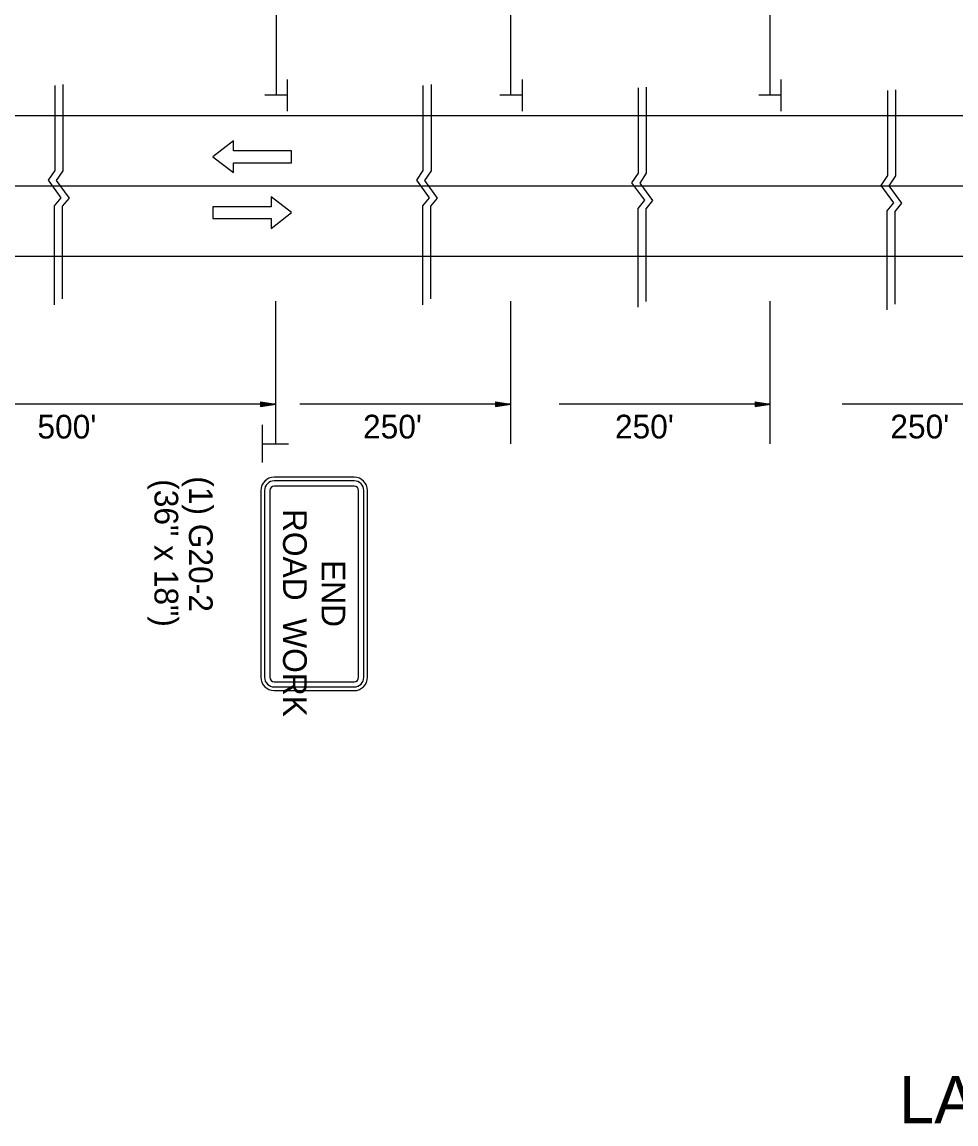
# Model space of a CAD drawing. Extents: x 1926586 to 1930787, y 596452 to 599566.
# Drawn here: x 1928093.9 to 1928330.2, y 596716.6 to 596995.4 of the extents above; entities that cross this region are included whole.
import ezdxf

# ---------------------------------------------------------------- set-up
doc = ezdxf.new("R2010")
doc.units = 0
for name, color, linetype in [('Default', 7, 'Continuous'), ('P_TC_Signs_Temporary', 7, 'Continuous'), ('R_Border', 7, 'Continuous'), ('R_Striping', 7, 'Continuous')]:
    doc.layers.add(name, color=color, linetype=linetype)

msp = doc.modelspace()

# ---------------------------------------------------------------- linework, layer by layer
at = {"layer": 'Default'}
for p, q in [((1928160.97, 596980.87), (1928160.97, 596972.87)), ((1928220.43, 596980.87), (1928220.43, 596972.87)), ((1928285.91, 596980.87), (1928285.91, 596972.87)), ((1928160.86, 596976.89), (1928155.39, 596976.89)), ((1928220.31, 596976.89), (1928214.85, 596976.89)), ((1928285.79, 596976.89), (1928280.32, 596976.89)), ((1927876.38, 596971.79), (1928531.8, 596971.74)), ((1927875.66, 596954), (1928669.64, 596953.94)), ((1927876.15, 596936.21), (1928531.8, 596936.16)), ((1928158.12, 596888.7), (1928158.12, 596924.73)), ((1928217.58, 596888.7), (1928217.58, 596924.73)), ((1928283.23, 596888.7), (1928283.23, 596924.73)), ((1928154.29, 596899.32), (1928158.12, 596898.74)), ((1928154.29, 596899.32), (1928154.29, 596898.16)), ((1928154.29, 596899.22), (1928157.48, 596898.74)), ((1928154.29, 596899.12), (1928156.82, 596898.74)), ((1928154.29, 596899.03), (1928156.18, 596898.74)), ((1928154.29, 596898.93), (1928155.53, 596898.74)), ((1928213.74, 596899.32), (1928217.58, 596898.74)), ((1928213.74, 596899.32), (1928213.74, 596898.16)), ((1928213.74, 596899.22), (1928216.94, 596898.74)), ((1928213.74, 596899.12), (1928216.28, 596898.74)), ((1928213.74, 596899.03), (1928215.64, 596898.74)), ((1928213.74, 596898.93), (1928214.99, 596898.74)), ((1928279.39, 596899.32), (1928283.23, 596898.74)), ((1928279.39, 596899.32), (1928279.39, 596898.16)), ((1928279.39, 596899.22), (1928282.59, 596898.74)), ((1928279.39, 596899.12), (1928281.93, 596898.74)), ((1928279.39, 596899.03), (1928281.29, 596898.74)), ((1928279.39, 596898.93), (1928280.64, 596898.74)), ((1928158.12, 596898.74), (1928058.37, 596898.74)), ((1928154.29, 596898.83), (1928154.89, 596898.74)), ((1928154.29, 596898.16), (1928158.12, 596898.74)), ((1928154.29, 596898.55), (1928155.53, 596898.74)), ((1928154.29, 596898.36), (1928156.82, 596898.74)), ((1928154.29, 596898.26), (1928157.48, 596898.74)), ((1928154.29, 596898.45), (1928156.18, 596898.74)), ((1928154.29, 596898.65), (1928154.89, 596898.74)), ((1928217.58, 596898.74), (1928164.18, 596898.74)), ((1928213.74, 596898.83), (1928214.35, 596898.74)), ((1928213.74, 596898.16), (1928217.58, 596898.74)), ((1928213.74, 596898.55), (1928214.99, 596898.74)), ((1928213.74, 596898.36), (1928216.28, 596898.74)), ((1928213.74, 596898.26), (1928216.94, 596898.74)), ((1928213.74, 596898.45), (1928215.64, 596898.74)), ((1928213.74, 596898.65), (1928214.35, 596898.74)), ((1928283.23, 596898.74), (1928229.83, 596898.74)), ((1928279.39, 596898.83), (1928280, 596898.74)), ((1928279.39, 596898.16), (1928283.23, 596898.74)), ((1928279.39, 596898.55), (1928280.64, 596898.74)), ((1928279.39, 596898.36), (1928281.93, 596898.74)), ((1928279.39, 596898.26), (1928282.59, 596898.74)), ((1928279.39, 596898.45), (1928281.29, 596898.74)), ((1928279.39, 596898.65), (1928280, 596898.74)), ((1928354.82, 596898.74), (1928301.42, 596898.74)), ((1928154.74, 596883.98), (1928154.74, 596893.47)), ((1928154.89, 596888.7), (1928161.36, 596888.7))]:
    msp.add_line(p, q, dxfattribs=at)
for points in [[(1928102.19, 596979.37), (1928102.19, 596957.85), (1928100.53, 596955.38), (1928103.77, 596950.95), (1928102.07, 596948.9), (1928102.06, 596923.88)], [(1928104.24, 596979.57), (1928104.24, 596957.77), (1928102.58, 596955.29), (1928105.81, 596950.86), (1928104.11, 596948.82), (1928104.11, 596925.32)], [(1928195.36, 596979.37), (1928195.36, 596957.85), (1928193.7, 596955.38), (1928196.93, 596950.95), (1928195.23, 596948.9), (1928195.23, 596923.88)], [(1928197.4, 596979.57), (1928197.4, 596957.77), (1928195.74, 596955.29), (1928198.98, 596950.86), (1928197.27, 596948.82), (1928197.27, 596925.32)], [(1928249.82, 596978.73), (1928249.82, 596957.2), (1928248.16, 596954.73), (1928251.4, 596950.3), (1928249.69, 596948.26), (1928249.69, 596923.23)], [(1928251.87, 596978.92), (1928251.87, 596957.12), (1928250.2, 596954.65), (1928253.44, 596950.22), (1928251.74, 596948.17), (1928251.73, 596924.67)], [(1928312.86, 596978.06), (1928312.86, 596956.53), (1928311.2, 596954.06), (1928314.44, 596949.63), (1928312.73, 596947.59), (1928312.73, 596922.56)], [(1928314.91, 596978.25), (1928314.91, 596956.45), (1928313.24, 596953.98), (1928316.48, 596949.55), (1928314.78, 596947.5), (1928314.77, 596924)]]:
    msp.add_lwpolyline(points, dxfattribs=at)
at = {"layer": 'P_TC_Signs_Temporary'}
for p, q in [((1928177.96, 596880.23), (1928157.71, 596880.23)), ((1928154.33, 596876.86), (1928154.33, 596829.61)), ((1928155.27, 596876.86), (1928155.27, 596829.61)), ((1928156.58, 596876.86), (1928156.58, 596829.61)), ((1928177.96, 596879.29), (1928157.71, 596879.29)), ((1928177.96, 596877.98), (1928157.71, 596877.98)), ((1928179.08, 596829.61), (1928179.08, 596876.86)), ((1928180.4, 596829.61), (1928180.4, 596876.86)), ((1928181.33, 596829.61), (1928181.33, 596876.86)), ((1928157.71, 596828.48), (1928177.96, 596828.48)), ((1928157.71, 596827.17), (1928177.96, 596827.17)), ((1928157.71, 596826.23), (1928177.96, 596826.23))]:
    msp.add_line(p, q, dxfattribs=at)
for centre, radius, start, end in [((1928157.71, 596876.86), 3.38, 90, 180), ((1928177.96, 596876.86), 3.37, 360, 90), ((1928157.71, 596876.86), 2.44, 90, 180), ((1928157.71, 596876.86), 1.13, 90, 180), ((1928177.96, 596876.86), 2.44, 360, 90), ((1928177.96, 596876.86), 1.13, 360, 90), ((1928157.71, 596829.61), 3.37, 180, 270), ((1928157.71, 596829.61), 2.44, 180, 270), ((1928157.71, 596829.61), 1.13, 180, 270), ((1928177.96, 596829.61), 2.44, 270, 360), ((1928177.96, 596829.61), 1.13, 270, 360), ((1928177.96, 596829.61), 3.38, 270, 360)]:
    msp.add_arc(centre, radius, start, end, dxfattribs=at)
at = {"layer": 'R_Border'}
for p, q in [((1928158.3, 596976.89), (1928158.3, 597053.66)), ((1928283.23, 596976.89), (1928283.23, 597051.44)), ((1928217.58, 596976.89), (1928217.58, 597010.2))]:
    msp.add_line(p, q, dxfattribs=at)
at = {"layer": 'R_Striping'}
for points in [[(1928147.39, 596965.3), (1928142.2, 596961.3), (1928147.39, 596957.3), (1928147.39, 596959.8), (1928162.11, 596959.8), (1928162.11, 596962.8), (1928147.39, 596962.8)], [(1928156.91, 596943.18), (1928162.11, 596947.18), (1928156.91, 596951.18), (1928156.91, 596948.68), (1928142.2, 596948.68), (1928142.2, 596945.68), (1928156.91, 596945.68)]]:
    msp.add_lwpolyline(points, close=True, dxfattribs=at)

# ---------------------------------------------------------------- texts
at = {"layer": 'Default'}
for s, height, rotation, p in [("500'", 6, 359.9922, (1928097.81, 596890.02)), ("250'", 6, 359.9922, (1928180.19, 596890.03)), ("250'", 6, 359.9922, (1928243.93, 596890.04)), ("250'", 6, 359.9922, (1928313.61, 596890.05)), ('LANE CLOSURE WITH PORTABLE TRAFFIC SIGNAL SYSTEM ', 12, 360, (1928315.81, 596716.75))]:
    msp.add_text(s, height=height, rotation=rotation, dxfattribs=at).set_placement(p)
at = {"layer": 'P_TC_Signs_Temporary'}
for s, p in [('ROAD  WORK', (1928159.96, 596872.19)), ('END', (1928169.71, 596859.26))]:
    msp.add_text(s, height=6, rotation=270, dxfattribs=at).set_placement(p)
at = {"layer": 'R_Border'}
for s, height, p in [('(1) G20-2', 6, (1928136.15, 596880.47)), ('(36" x 18")', 5.9996, (1928127.43, 596879.72))]:
    msp.add_text(s, height=height, rotation=270, dxfattribs=at).set_placement(p)

doc.saveas('drawing.dxf')
